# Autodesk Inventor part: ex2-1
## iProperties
Shininess: 64.0
Length Units: 11272
Angle Units: 11279
Time Units: 11290
Mass Units: 11286
Length Display Precision: 3
Angle Display Precision: 2
Compacted: True
Part Number: ex2-1
Document SubType Name: Modeling
Created: 2003-11
Designer: Elise Moss
Cost Center: 0.4 lbmass
Authority: 11.8 in^3
Manufacturer: Standard
Standards Organization: Custom
Density: 0.0
Volumn: 0.0
Area: 0.0
PropertySet Name: Model Information
Control State: 0
Master: False
Checked Out: False
SaveDate: 2003-11-10
SaveTime: 12:14
TotalMass: 0.4 lbmass
TotalVolume: 11.8 in^3
Author: Elise Moss
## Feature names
1. Extrusion1
